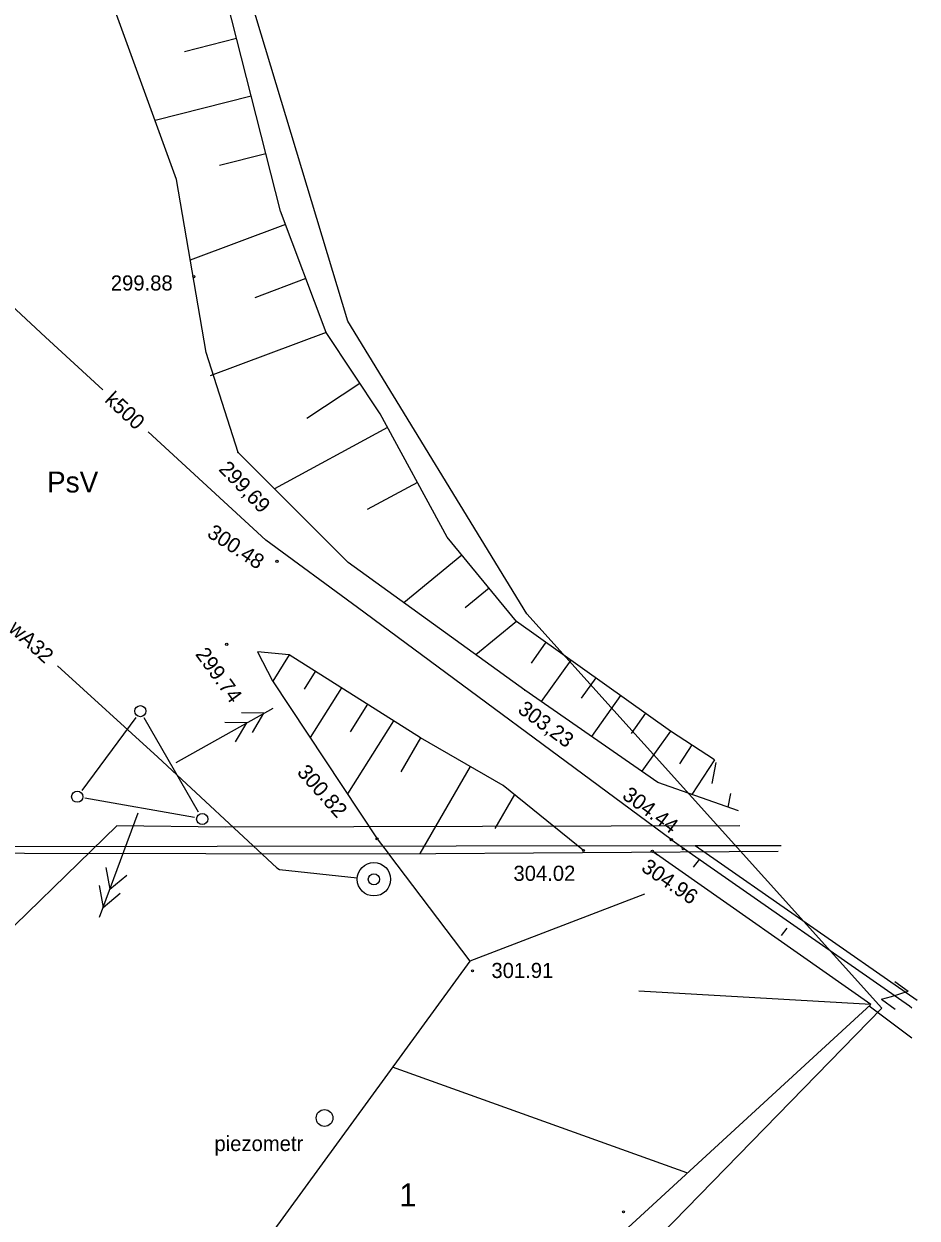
# Model space of a CAD drawing. Extents: x 7477803 to 7478145, y 5500698 to 5500984.
# Drawn here: x 7478053.5 to 7478093.7, y 5500810.8 to 5500864.5 of the extents above; entities that cross this region are included whole.
import ezdxf

# ---------------------------------------------------------------- set-up
doc = ezdxf.new("R2010")
doc.units = 0
for name, color, linetype in [('e_linia_podpora', 7, 'Continuous'), ('e_Proj', 7, 'Continuous'), ('e_slupy', 7, 'Continuous'), ('gr_klasy', 7, 'Continuous'), ('gr_uzytek', 7, 'Continuous'), ('k', 7, 'Continuous'), ('k_opis', 7, 'Continuous'), ('nr_dzialki', 7, 'Continuous'), ('ogr_symb', 7, 'Continuous'), ('opis_klasy', 7, 'Continuous'), ('pkt_wys', 7, 'Continuous'), ('przehaczenie', 7, 'Continuous'), ('robocza38', 7, 'Continuous'), ('rowy', 7, 'Continuous'), ('skarp_wypel', 7, 'Continuous'), ('skarpa_dol', 7, 'Continuous'), ('skarpa_gora', 7, 'Continuous'), ('w', 7, 'Continuous'), ('w_elem_naziemne', 7, 'Continuous'), ('w_opis', 7, 'Continuous'), ('zakresy', 7, 'Continuous')]:
    doc.layers.add(name, color=color, linetype=linetype)

# ---------------------------------------------------------------- blocks, each defined once
blk = doc.blocks.new('506')
at = {"layer": 'robocza38'}
blk.add_circle((0, 0), 0.3, dxfattribs=at)
blk = doc.blocks.new('511_5')
at = {"layer": 'e_slupy'}
blk.add_circle((0, 0), 0.25, dxfattribs=at)
blk = doc.blocks.new('907_5')
at = {"layer": 'w_elem_naziemne'}
for radius in [0.75, 0.25]:
    blk.add_circle((0, 0), radius, dxfattribs=at)
blk = doc.blocks.new('140_1')
at = {"layer": 'pkt_wys'}
blk.add_circle((0, 0), 0.045, dxfattribs=at)
blk.add_circle((0, 0), 0.045, dxfattribs=at)
blk = doc.blocks.new('140')
at = {"layer": 'pkt_wys'}
blk.add_circle((0, 0), 0.045, dxfattribs=at)
blk.add_circle((0, 0), 0.045, dxfattribs=at)
blk = doc.blocks.new('801_1')
at = {"layer": 'pkt_wys'}
blk.add_circle((0, 0), 0.045, dxfattribs=at)
blk.add_circle((0, 0), 0.045, dxfattribs=at)
blk = doc.blocks.new('801_5')
at = {"layer": 'pkt_wys'}
blk.add_circle((0, 0), 0.05, dxfattribs=at)
blk.add_circle((0, 0), 0.05, dxfattribs=at)
blk = doc.blocks.new('801_5_4')
at = {"layer": 'pkt_wys'}
blk.add_circle((0, 0), 0.05, dxfattribs=at)
blk.add_circle((0, 0), 0.05, dxfattribs=at)
blk = doc.blocks.new('SUPE03')
at = {"layer": 'e_slupy'}
for p, q in [((5, 0), (105, 0)), ((78, 0), (60.7, 10)), ((60.7, -10), (78, 0)), ((95.3, 0), (78, 10)), ((78, -10), (95.3, 0))]:
    blk.add_line(p, q, dxfattribs=at)
blk = doc.blocks.new('SUPE3')
at = {"layer": 'e_slupy', "xscale": 0.05, "yscale": 0.05000000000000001}
blk.add_blockref('SUPE03', (0, 0), dxfattribs=at)

msp = doc.modelspace()

# ---------------------------------------------------------------- linework, layer by layer
at = {"layer": 'e_linia_podpora'}
for p, q in [((7478058.571, 5500833.33), (7478056.15, 5500830.043)), ((7478061.386, 5500829.065), (7478058.953, 5500833.309)), ((7478061.216, 5500828.823), (7478056.287, 5500829.7))]:
    msp.add_line(p, q, dxfattribs=at)
at = {"layer": 'e_Proj'}
msp.add_lwpolyline([(7478085.721, 5500828.46), (7478062.59, 5500828.394), (7478057.723, 5500828.457), (7478045.093, 5500816.16), (7478029.949, 5500801.309), (7478024.948, 5500777.245), (7478020.357, 5500757.697), (7478013.921, 5500735.554), (7478010.536, 5500720.256)], dxfattribs=at)
at = {"layer": 'gr_klasy'}
for points in [[(7478040.73, 5500827.51), (7478083.71, 5500827.57)], [(7478083.71, 5500827.57), (7478087.585, 5500827.576)]]:
    msp.add_lwpolyline(points, dxfattribs=at)
at = {"layer": 'gr_uzytek'}
msp.add_line((7478083.71, 5500827.57), (7478093.691, 5500820.623), dxfattribs=at)
at = {"layer": 'k'}
for points in [[(7478057.09, 5500848.054), (7478054.513, 5500850.429), (7478052.301, 5500852.476)], [(7478082.641, 5500827.836), (7478068.543, 5500838.264), (7478064.419, 5500841.298), (7478059.132, 5500846.172)]]:
    msp.add_lwpolyline(points, dxfattribs=at)
at = {"layer": 'ogr_symb'}
for points in [[(7478026.319, 5500802.715), (7478028.17, 5500804.079), (7478034.551, 5500808.191), (7478045.422, 5500827.246), (7478069.852, 5500827.202)], [(7478069.852, 5500827.202), (7478087.448, 5500827.322)]]:
    msp.add_lwpolyline(points, dxfattribs=at)
at = {"layer": 'przehaczenie'}
for p, q in [((7478092.684, 5500821.461), (7478093.289, 5500821.019)), ((7478092.093, 5500820.654), (7478092.534, 5500820.788)), ((7478092.534, 5500820.788), (7478093.289, 5500821.019)), ((7478092.093, 5500820.654), (7478092.699, 5500820.211))]:
    msp.add_line(p, q, dxfattribs=at)
at = {"layer": 'rowy'}
for p, q in [((7478082.641, 5500827.836), (7478083.593, 5500827.172)), ((7478083.593, 5500827.172), (7478093.348, 5500820.356))]:
    msp.add_line(p, q, dxfattribs=at)
msp.add_lwpolyline([(7478093.348, 5500820.356), (7478093.45, 5500820.276)], dxfattribs=at)
at = {"layer": 'skarp_wypel'}
for p, q in [((7478063.107, 5500863.853), (7478060.764, 5500863.258)), ((7478063.765, 5500861.264), (7478059.441, 5500860.166)), ((7478064.423, 5500858.676), (7478062.33, 5500858.144)), ((7478065.305, 5500855.488), (7478061.025, 5500853.881)), ((7478066.216, 5500853.064), (7478063.918, 5500852.201)), ((7478067.126, 5500850.639), (7478061.92, 5500848.684)), ((7478068.647, 5500848.348), (7478066.269, 5500846.77)), ((7478069.892, 5500846.362), (7478064.811, 5500843.603)), ((7478071.229, 5500843.898), (7478068.971, 5500842.672)), ((7478073.23, 5500840.629), (7478070.62, 5500838.482)), ((7478074.455, 5500839.139), (7478073.375, 5500838.25)), ((7478075.681, 5500837.649), (7478073.854, 5500836.146)), ((7478077.004, 5500836.706), (7478076.338, 5500835.771)), ((7478065.472, 5500836.137), (7478064.732, 5500834.964)), ((7478078.124, 5500835.908), (7478076.795, 5500834.042)), ((7478066.644, 5500835.399), (7478066.137, 5500834.595)), ((7478079.245, 5500835.11), (7478078.588, 5500834.188)), ((7478067.815, 5500834.66), (7478066.408, 5500832.429)), ((7478080.365, 5500834.312), (7478079.056, 5500832.474)), ((7478068.986, 5500833.921), (7478068.204, 5500832.682)), ((7478070.157, 5500833.183), (7478068.084, 5500829.895)), ((7478081.486, 5500833.514), (7478080.838, 5500832.605)), ((7478082.606, 5500832.716), (7478081.317, 5500830.906)), ((7478071.376, 5500832.414), (7478070.492, 5500830.884)), ((7478083.56, 5500832.091), (7478083.007, 5500831.247)), ((7478073.608, 5500831.124), (7478071.347, 5500827.212)), ((7478084.587, 5500831.418), (7478083.571, 5500829.867)), ((7478084.643, 5500831.301), (7478084.464, 5500830.354)), ((7478085.3, 5500829.912), (7478085.184, 5500829.3)), ((7478075.592, 5500829.859), (7478074.708, 5500828.329)), ((7478083.642, 5500826.595), (7478083.906, 5500826.948)), ((7478083.906, 5500826.948), (7478083.907, 5500826.95)), ((7478081.444, 5500825.384), (7478073.588, 5500822.37)), ((7478087.597, 5500823.529), (7478087.852, 5500823.859)), ((7478091.611, 5500820.417), (7478081.188, 5500821.015)), ((7478083.339, 5500812.851), (7478070.116, 5500817.603))]:
    msp.add_line(p, q, dxfattribs=at)
at = {"layer": 'skarpa_dol'}
for points in [[(7478085.67, 5500829.13), (7478082.039, 5500830.406), (7478076.064, 5500834.549), (7478068.118, 5500840.29), (7478063.172, 5500845.245), (7478061.737, 5500849.743), (7478060.399, 5500857.522), (7478056.036, 5500869.567), (7478053.569, 5500876.194), (7478045.187, 5500887.165), (7478041.832, 5500891.272), (7478041.129, 5500893.791), (7478036.961, 5500900.926), (7478035.06, 5500902.704), (7478029.997, 5500905.289)], [(7478064.052, 5500836.276), (7478064.724, 5500834.977), (7478069.421, 5500827.872)]]:
    msp.add_lwpolyline(points, dxfattribs=at)
at = {"layer": 'skarpa_gora'}
msp.add_line((7478093.451, 5500818.91), (7478091.537, 5500820.353), dxfattribs=at)
for points in [[(7478084.587, 5500831.418), (7478082.606, 5500832.716), (7478075.681, 5500837.649), (7478072.567, 5500841.435), (7478069.56, 5500846.972), (7478067.126, 5500850.639), (7478065.081, 5500856.087), (7478061.796, 5500869.013), (7478060.722, 5500873.092), (7478053.569, 5500876.194)], [(7478078.692, 5500827.342), (7478075.089, 5500830.268), (7478071.376, 5500832.414), (7478065.472, 5500836.137), (7478064.052, 5500836.276)], [(7478069.421, 5500827.872), (7478069.96, 5500827.16)], [(7478069.928, 5500827.203), (7478073.588, 5500822.37), (7478057.135, 5500799.786), (7478043.065, 5500780.842), (7478042.62, 5500779.665), (7478041.951, 5500775.41), (7478040.823, 5500767.601), (7478039.347, 5500758.051)], [(7478053.931, 5500779.44), (7478058.547, 5500785.559), (7478063.881, 5500792.399), (7478066.961, 5500796.071), (7478077.177, 5500807.154), (7478091.611, 5500820.417), (7478081.823, 5500827.284)], [(7478082.024, 5500827.143), (7478081.792, 5500827.305)]]:
    msp.add_lwpolyline(points, dxfattribs=at)
at = {"layer": 'w'}
msp.add_lwpolyline([(7478055.06, 5500835.655), (7478059.57, 5500831.535), (7478064.917, 5500826.573), (7478065.031, 5500826.492), (7478068.521, 5500826.115)], dxfattribs=at)
at = {"layer": 'zakresy'}
msp.add_lwpolyline([(7477995.059, 5500962.348), (7477983.951, 5500968.084), (7477970.781, 5500968.613), (7477936.09, 5500958.171), (7477930.511, 5500954.336), (7477914.305, 5500958.58), (7477904.32, 5500957.41), (7477897.265, 5500950.868), (7477811.424, 5500829.338), (7477936.003, 5500769.492), (7478008.982, 5500726.585), (7478019.402, 5500721.781), (7478037.95, 5500734.97), (7478039.493, 5500755.094), (7478043.98, 5500765.708), (7478067.545, 5500795.068), (7478092.109, 5500820.25), (7478076.156, 5500837.989), (7478068.105, 5500851.146), (7478061.422, 5500873.298), (7478054.135, 5500876.371), (7478039.669, 5500897.644), (7478026.36, 5500915.23), (7478015.054, 5500927.728)], close=True, dxfattribs=at)

# ---------------------------------------------------------------- block references
at = {"layer": 'e_slupy'}
for name, p, rotation in [('SUPE3', (7478060.169, 5500831.187), 29.23596345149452), ('511_5', (7478058.779, 5500833.612), 0.0626175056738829), ('511_5', (7478055.942, 5500829.762), 0.0626175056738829), ('SUPE3', (7478058.751, 5500829.261), -110.23171118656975), ('511_5', (7478061.56, 5500828.761), 0.0626175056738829)]:
    msp.add_blockref(name, p, dxfattribs=dict(at, rotation=rotation))
at = {"layer": 'pkt_wys', "rotation": 0.0626175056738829}
for name, p in [('801_5', (7478061.184, 5500853.143)), ('801_5', (7478064.918, 5500840.347)), ('801_5', (7478062.662, 5500836.614)), ('801_5', (7478069.421, 5500827.872)), ('801_5', (7478082.641, 5500827.836)), ('801_1', (7478078.692, 5500827.342)), ('801_5', (7478081.792, 5500827.305)), ('801_1', (7478083.182, 5500827.417)), ('140_1', (7478073.703, 5500821.935)), ('140', (7478080.49, 5500811.102))]:
    msp.add_blockref(name, p, dxfattribs=at)
at = {"layer": 'pkt_wys', "xscale": 0.25, "yscale": 0.24999999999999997, "rotation": 0.0626175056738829}
for p in [(7478063.172, 5500845.245), (7478076.064, 5500834.549)]:
    msp.add_blockref('801_5_4', p, dxfattribs=at)
at = {"layer": 'robocza38', "xscale": 1.2539698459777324, "yscale": 1.2539698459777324, "rotation": 0.06261750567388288}
msp.add_blockref('506', (7478067.059, 5500815.319), dxfattribs=at)
at = {"layer": 'w_elem_naziemne', "rotation": 0.0626175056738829}
msp.add_blockref('907_5', (7478069.276, 5500826.05), dxfattribs=at)

# ---------------------------------------------------------------- texts
at = {"layer": 'k_opis'}
msp.add_text('k500', height=0.68, rotation=317.3319, dxfattribs=at).set_placement((7478057.135, 5500847.55))
at = {"layer": 'nr_dzialki'}
msp.add_text('1', height=1.04, dxfattribs=at).set_placement((7478070.417, 5500811.342))
at = {"layer": 'opis_klasy'}
msp.add_text('PsV', height=0.94, dxfattribs=at).set_placement((7478054.584, 5500843.444))
at = {"layer": 'pkt_wys'}
for s, rotation, p in [('299.88', 0.0626, (7478057.452, 5500852.522)), ('299,69', 314.039, (7478062.264, 5500844.461)), ('300.48', 326.5734, (7478061.733, 5500841.489)), ('299.74', 305.7693, (7478061.223, 5500836.169)), ('303,23', 323.516, (7478075.697, 5500833.583)), ('300.82', 311.5591, (7478065.786, 5500830.839)), ('304.44', 323.5489, (7478080.392, 5500829.719)), ('304.02', 0.0626, (7478075.549, 5500825.98)), ('304.96', 325.3675, (7478081.245, 5500826.464)), ('301.91', 0.0626, (7478074.559, 5500821.612))]:
    msp.add_text(s, height=0.68, rotation=rotation, dxfattribs=at).set_placement(p)
at = {"layer": 'robocza38'}
msp.add_text('piezometr', height=0.68, rotation=0.0626, dxfattribs=at).set_placement((7478062.11, 5500813.83))
at = {"layer": 'w_opis'}
msp.add_text('wA32', height=0.68, rotation=317.5858, dxfattribs=at).set_placement((7478052.81, 5500837.251))

doc.saveas('drawing.dxf')
